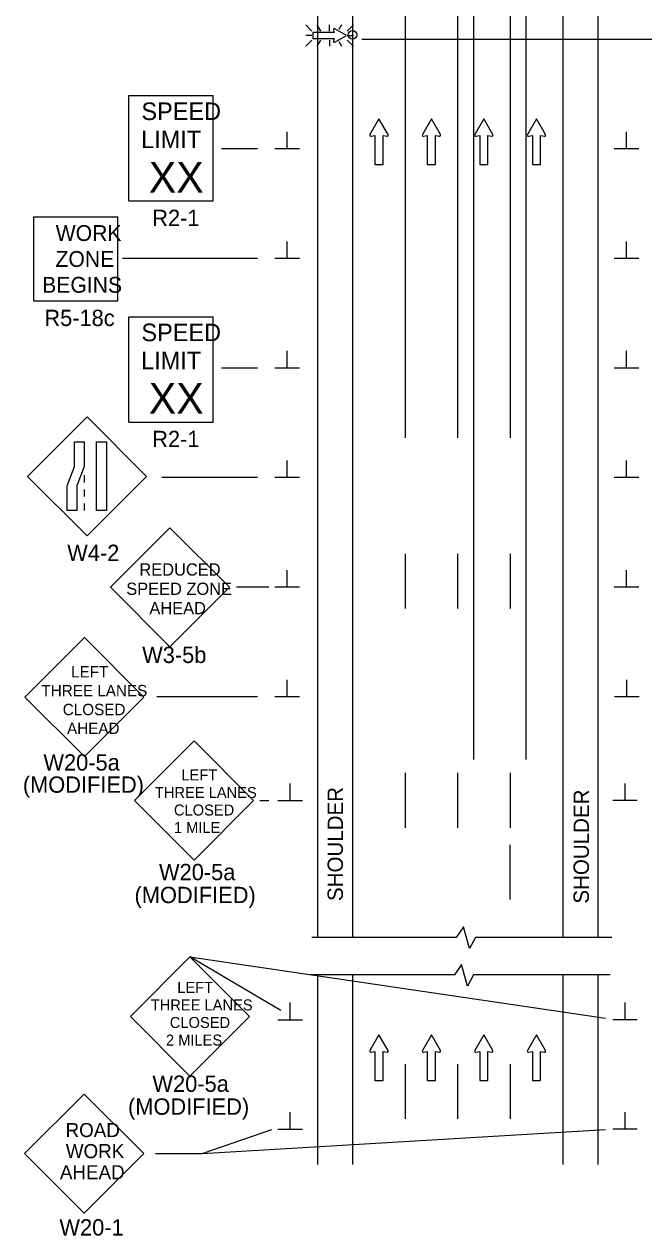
# Model space of a CAD drawing. Extents: x 16725 to 18479, y 5932 to 7023.
# Drawn here: x 16725 to 17008, y 5959 to 6512 of the extents above; entities that cross this region are included whole.
import ezdxf

# ---------------------------------------------------------------- set-up
doc = ezdxf.new("R2010")
doc.units = 0
for name, color, linetype in [('ALI_LEGAL_EX', 7, 'Continuous'), ('MT_SCRATCH_LEVEL_E', 7, 'Continuous'), ('PAVT_EDGE_EX', 7, 'Continuous'), ('TRAFFIC_SIGNS_PR', 7, 'Continuous'), ('TYPICAL_TEXT_DIMEN_PR', 7, 'Continuous')]:
    doc.layers.add(name, color=color, linetype=linetype)

msp = doc.modelspace()

# ---------------------------------------------------------------- linework, layer by layer
at = {"layer": 'ALI_LEGAL_EX'}
for p, q in [((16898.69, 7022.86), (16898.69, 6323.13)), ((16922.69, 7022.86), (16922.69, 6323.13)), ((16946.69, 7022.86), (16946.69, 6323.13)), ((16929.88, 7005.57), (16929.88, 6176.39)), ((16953.88, 7005.57), (16953.88, 6176.39)), ((16953.88, 7005.57), (16953.88, 6176.39))]:
    msp.add_line(p, q, dxfattribs=at)
for points in [[(16898.69, 6470.26), (16898.69, 6445.26)], [(16922.69, 6470.26), (16922.69, 6445.26)], [(16946.69, 6470.26), (16946.69, 6445.26)], [(16898.69, 6370.26), (16898.69, 6345.26)], [(16922.69, 6370.26), (16922.69, 6345.26)], [(16946.69, 6370.26), (16946.69, 6345.26)], [(16898.69, 6270.26), (16898.69, 6245.26)], [(16922.69, 6270.26), (16922.69, 6245.26)], [(16946.69, 6270.26), (16946.69, 6245.26)], [(16898.69, 6170.26), (16898.69, 6145.26)], [(16922.69, 6170.26), (16922.69, 6145.26)], [(16946.69, 6170.26), (16946.69, 6145.26)], [(16946.69, 6112.44), (16946.69, 6137.44)], [(16898.69, 6037.44), (16898.69, 6012.44)], [(16922.69, 6037.44), (16922.69, 6012.44)], [(16946.69, 6037.44), (16946.69, 6012.44)]]:
    msp.add_lwpolyline(points, dxfattribs=at)
at = {"layer": 'MT_SCRATCH_LEVEL_E'}
for p, q in [((16886.79, 6468.72), (16882.68, 6461.48)), ((16890.94, 6461.48), (16886.79, 6468.72)), ((16910.69, 6468.72), (16906.58, 6461.48)), ((16914.84, 6461.48), (16910.69, 6468.72)), ((16934.6, 6468.72), (16930.49, 6461.48)), ((16938.74, 6461.48), (16934.6, 6468.72)), ((16958.65, 6468.72), (16954.54, 6461.48)), ((16962.8, 6461.48), (16958.65, 6468.72)), ((16883.16, 6460.79), (16884.94, 6461.11)), ((16884.94, 6461.11), (16884.94, 6447.85)), ((16888.68, 6447.85), (16888.68, 6461.11)), ((16888.68, 6461.11), (16890.46, 6460.79)), ((16907.06, 6460.79), (16908.84, 6461.11)), ((16908.84, 6461.11), (16908.84, 6447.85)), ((16912.58, 6447.85), (16912.58, 6461.11)), ((16912.58, 6461.11), (16914.36, 6460.79)), ((16930.97, 6460.79), (16932.74, 6461.11)), ((16932.74, 6461.11), (16932.74, 6447.85)), ((16936.49, 6447.85), (16936.49, 6461.11)), ((16936.49, 6461.11), (16938.26, 6460.79)), ((16955.02, 6460.79), (16956.8, 6461.11)), ((16956.8, 6461.11), (16956.8, 6447.85)), ((16960.54, 6447.85), (16960.54, 6461.11)), ((16960.54, 6461.11), (16962.32, 6460.79)), ((16884.94, 6447.85), (16888.68, 6447.85)), ((16908.84, 6447.85), (16912.58, 6447.85)), ((16932.74, 6447.85), (16936.49, 6447.85)), ((16956.8, 6447.85), (16960.54, 6447.85)), ((16886.79, 6050.8), (16882.68, 6043.56)), ((16890.94, 6043.56), (16886.79, 6050.8)), ((16910.69, 6050.8), (16906.58, 6043.56)), ((16914.84, 6043.56), (16910.69, 6050.8)), ((16934.6, 6050.8), (16930.49, 6043.56)), ((16938.74, 6043.56), (16934.6, 6050.8)), ((16958.65, 6050.8), (16954.54, 6043.56)), ((16962.8, 6043.56), (16958.65, 6050.8)), ((16883.16, 6042.87), (16884.94, 6043.19)), ((16884.94, 6043.19), (16884.94, 6029.93)), ((16888.68, 6029.93), (16888.68, 6043.19)), ((16888.68, 6043.19), (16890.46, 6042.87)), ((16907.06, 6042.87), (16908.84, 6043.19)), ((16908.84, 6043.19), (16908.84, 6029.93)), ((16912.58, 6029.93), (16912.58, 6043.19)), ((16912.58, 6043.19), (16914.36, 6042.87)), ((16930.97, 6042.87), (16932.74, 6043.19)), ((16932.74, 6043.19), (16932.74, 6029.93)), ((16936.49, 6029.93), (16936.49, 6043.19)), ((16936.49, 6043.19), (16938.26, 6042.87)), ((16955.02, 6042.87), (16956.8, 6043.19)), ((16956.8, 6043.19), (16956.8, 6029.93)), ((16960.54, 6029.93), (16960.54, 6043.19)), ((16960.54, 6043.19), (16962.32, 6042.87)), ((16884.94, 6029.93), (16888.68, 6029.93)), ((16908.84, 6029.93), (16912.58, 6029.93)), ((16932.74, 6029.93), (16936.49, 6029.93)), ((16956.8, 6029.93), (16960.54, 6029.93))]:
    msp.add_line(p, q, dxfattribs=at)
for centre, start, end in [((16883.09, 6461.25), 150.4248, 279.9638), ((16890.53, 6461.25), 260.0362, 29.7731), ((16906.99, 6461.25), 150.4248, 279.9638), ((16914.43, 6461.25), 260.0362, 29.7731), ((16930.89, 6461.25), 150.4248, 279.9638), ((16938.33, 6461.25), 260.0362, 29.7731), ((16954.95, 6461.25), 150.4248, 279.9638), ((16962.39, 6461.25), 260.0362, 29.7731), ((16883.09, 6043.33), 150.4248, 279.9638), ((16890.53, 6043.33), 260.0362, 29.7731), ((16906.99, 6043.33), 150.4248, 279.9638), ((16914.43, 6043.33), 260.0362, 29.7731), ((16930.89, 6043.33), 150.4248, 279.9638), ((16938.33, 6043.33), 260.0362, 29.7731), ((16954.95, 6043.33), 150.4248, 279.9638), ((16962.39, 6043.33), 260.0362, 29.7731)]:
    msp.add_arc(centre, 0.463, start, end, dxfattribs=at)
at = {"layer": 'PAVT_EDGE_EX'}
for p, q in [((16858.69, 6927.61), (16858.69, 6189.52)), ((16874.69, 6927.61), (16874.69, 6189.52)), ((16970.69, 6927.61), (16970.69, 6189.52)), ((16986.69, 6927.61), (16986.69, 6189.52)), ((16858.69, 6189.52), (16858.69, 6095.26)), ((16874.69, 6189.52), (16874.69, 6095.26)), ((16970.69, 6189.52), (16970.69, 6095.25)), ((16986.69, 6189.52), (16986.69, 6095.25)), ((16858.69, 6078.1), (16858.69, 5991.64)), ((16874.69, 6078.1), (16874.69, 5991.64)), ((16970.69, 6078.11), (16970.69, 5991.64)), ((16986.69, 6078.11), (16986.69, 5991.64))]:
    msp.add_line(p, q, dxfattribs=at)
at = {"layer": 'TRAFFIC_SIGNS_PR'}
for p, q in [((16856.17, 6508.7), (16853.35, 6511.52)), ((16858.47, 6511.52), (16860.1, 6508.7)), ((16864.26, 6508.7), (16864.26, 6511.52)), ((16869.73, 6511.52), (16868.52, 6509.43)), ((16875.16, 6511.52), (16872.34, 6508.7)), ((16856.17, 6506.67), (16853.35, 6506.67)), ((16872.34, 6506.67), (16875.16, 6506.67)), ((16856.17, 6504.64), (16853.35, 6501.81)), ((16860.12, 6504.64), (16858.49, 6501.82)), ((16864.26, 6504.64), (16864.26, 6501.82)), ((16868.44, 6504), (16869.7, 6501.82)), ((16875.16, 6501.82), (16872.34, 6504.64)), ((16772.61, 6479.27), (16811.05, 6479.27)), ((16772.61, 6431.21), (16772.61, 6479.27)), ((16811.05, 6431.21), (16811.05, 6479.27)), ((16772.61, 6431.21), (16811.05, 6431.21)), ((16729.26, 6385.58), (16729.26, 6423.98)), ((16729.26, 6423.98), (16767.66, 6423.98)), ((16767.66, 6385.58), (16767.66, 6423.98)), ((16729.26, 6385.58), (16767.66, 6385.58)), ((16772.61, 6378.4), (16811.06, 6378.4)), ((16772.61, 6330.34), (16772.61, 6378.4)), ((16811.06, 6330.34), (16811.06, 6378.4)), ((16753.55, 6332.69), (16726.39, 6305.54)), ((16780.7, 6305.54), (16753.55, 6332.69)), ((16772.61, 6330.34), (16811.06, 6330.34)), ((16726.39, 6305.54), (16753.55, 6278.39)), ((16752.3, 6306.03), (16752.3, 6302.83)), ((16753.55, 6278.39), (16780.7, 6305.54)), ((16752.3, 6299.63), (16752.3, 6296.43)), ((16752.3, 6293.23), (16752.3, 6290.03)), ((16791.39, 6282.1), (16764.24, 6254.95)), ((16818.55, 6254.95), (16791.39, 6282.1)), ((16764.24, 6254.95), (16791.39, 6227.8)), ((16791.39, 6227.8), (16818.55, 6254.95)), ((16752.34, 6232.01), (16725.19, 6204.86)), ((16779.5, 6204.86), (16752.34, 6232.01)), ((16725.19, 6204.86), (16752.34, 6177.7)), ((16752.34, 6177.7), (16779.5, 6204.86)), ((16802.37, 6184.87), (16775.19, 6157.68)), ((16829.56, 6157.68), (16802.37, 6184.87)), ((16775.19, 6157.68), (16802.37, 6130.5)), ((16802.37, 6130.5), (16829.56, 6157.68)), ((16800.49, 6086.29), (16773.31, 6059.11)), ((16827.68, 6059.11), (16800.49, 6086.29)), ((16773.31, 6059.11), (16800.49, 6031.92)), ((16800.49, 6031.92), (16827.68, 6059.11)), ((16752.23, 6023.74), (16725.04, 5996.56)), ((16779.42, 5996.56), (16752.23, 6023.74)), ((16725.04, 5996.56), (16752.23, 5969.37)), ((16752.23, 5969.37), (16779.42, 5996.56))]:
    msp.add_line(p, q, dxfattribs=at)
for points in [[(16866.08, 6509.35), (16866.31, 6508.05), (16856.59, 6508.05), (16856.59, 6505.31), (16866.31, 6505.31), (16866.08, 6504.01)], [(16866.58, 6503.65), (16871.89, 6506.67), (16866.58, 6509.71)]]:
    msp.add_lwpolyline(points, dxfattribs=at)
for points in [[(16752.3, 6321.28), (16752.3, 6310.1), (16748.95, 6301.21), (16748.95, 6290.03), (16744.46, 6290.03), (16744.46, 6301.21), (16747.8, 6310.1), (16747.8, 6321.28)], [(16762.43, 6321.28), (16762.43, 6290.03), (16757.94, 6290.03), (16757.94, 6321.28)]]:
    msp.add_lwpolyline(points, close=True, dxfattribs=at)
msp.add_circle((16874.7, 6507.03), 2, dxfattribs=at)
for centre, start, end in [((16866.42, 6509.41), 61.4833, 189.9593), ((16866.42, 6503.95), 170.7308, 298.8916)]:
    msp.add_arc(centre, 0.341, start, end, dxfattribs=at)
at = {"layer": 'TYPICAL_TEXT_DIMEN_PR'}
for p, q in [((16878.96, 6504.98), (17062.74, 6504.98)), ((16907.09, 6504.98), (17061.13, 6504.98)), ((16844.81, 6454.98), (16844.81, 6462.77)), ((16999.82, 6454.98), (16999.82, 6462.77)), ((16831.38, 6454.98), (16814.89, 6454.98)), ((16850.44, 6454.98), (16839.19, 6454.98)), ((17005.44, 6454.98), (16994.19, 6454.98)), ((16844.81, 6404.98), (16844.81, 6412.77)), ((16999.82, 6404.98), (16999.82, 6412.77)), ((16831.38, 6404.98), (16769.78, 6404.98)), ((16850.44, 6404.98), (16839.19, 6404.98)), ((17005.44, 6404.98), (16994.19, 6404.98)), ((16844.81, 6354.98), (16844.81, 6362.77)), ((16999.82, 6354.98), (16999.82, 6362.77)), ((16831.38, 6354.98), (16814.89, 6354.98)), ((16850.44, 6354.98), (16839.19, 6354.98)), ((17005.44, 6354.98), (16994.19, 6354.98)), ((16844.81, 6304.98), (16844.81, 6312.77)), ((16999.82, 6304.98), (16999.82, 6312.77)), ((16831.38, 6304.98), (16787.72, 6304.98)), ((16850.44, 6304.98), (16839.19, 6304.98)), ((17005.44, 6304.98), (16994.19, 6304.98)), ((16844.81, 6254.98), (16844.81, 6262.77)), ((16999.82, 6254.98), (16999.82, 6262.77)), ((16836.48, 6254.98), (16821.8, 6254.98)), ((16850.44, 6254.98), (16839.19, 6254.98)), ((17005.44, 6254.98), (16994.19, 6254.98)), ((16844.95, 6204.98), (16844.95, 6212.77)), ((16999.96, 6204.98), (16999.96, 6212.77)), ((16831.38, 6204.98), (16785.46, 6204.98)), ((16850.57, 6204.98), (16839.32, 6204.98)), ((17005.58, 6204.98), (16994.33, 6204.98)), ((16846.32, 6157.67), (16846.32, 6165.46)), ((16999.07, 6157.67), (16999.07, 6165.46)), ((16836.48, 6157.57), (16832.38, 6157.57)), ((16840.69, 6157.67), (16851.94, 6157.67)), ((17004.69, 6157.67), (16993.44, 6157.67)), ((16925.31, 6100.03), (16922.05, 6095.23)), ((16928.05, 6090.1), (16925.31, 6100.03)), ((16922.05, 6095.23), (16856.11, 6095.23)), ((16930.79, 6095.23), (16928.05, 6090.1)), ((16993.12, 6095.23), (16930.79, 6095.23)), ((16841.93, 6061.85), (16800.49, 6086.29)), ((16800.49, 6086.29), (16990.17, 6058.35)), ((16924.51, 6082.9), (16921.25, 6078.1)), ((16927.25, 6072.96), (16924.51, 6082.9)), ((16921.25, 6078.1), (16855.31, 6078.1)), ((16929.99, 6078.1), (16927.25, 6072.96)), ((16992.32, 6078.1), (16929.99, 6078.1)), ((16846.32, 6057.67), (16846.32, 6065.46)), ((16999.07, 6057.67), (16999.07, 6065.46)), ((16840.69, 6057.67), (16851.94, 6057.67)), ((17004.69, 6057.67), (16993.44, 6057.67)), ((16846.32, 6007.67), (16846.32, 6015.46)), ((16999.07, 6007.67), (16999.07, 6015.46)), ((16806.09, 5996.56), (16837.85, 6007.58)), ((16806.09, 5996.56), (16990.17, 6007.58)), ((16840.69, 6007.67), (16851.94, 6007.67)), ((17004.69, 6007.67), (16993.44, 6007.67)), ((16784.83, 5996.56), (16806.09, 5996.56))]:
    msp.add_line(p, q, dxfattribs=at)

# ---------------------------------------------------------------- texts
at = {"layer": 'TRAFFIC_SIGNS_PR'}
for s, height, p in [('SPEED', 8.01, (16778.38, 6468.12)), ('LIMIT', 8.01, (16778.22, 6455.31)), ('XX', 14.048, (16781.73, 6434.98)), ('R2-1', 7.449, (16783.3, 6419.76)), ('WORK', 7.217, (16739.26, 6412.95)), ('ZONE', 7.217, (16739.15, 6401.14)), ('BEGINS', 7.217, (16733.07, 6389.33)), ('R5-18c', 7.44, (16734.08, 6374.14)), ('SPEED', 8.01, (16778.38, 6367.24)), ('LIMIT', 8.01, (16778.22, 6354.43)), ('XX', 14.048, (16781.73, 6334.1)), ('R2-1', 7.449, (16783.3, 6318.88)), ('W4-2', 7.44, (16744.5, 6266.95)), ('REDUCED', 5.6, (16777.45, 6260.26)), ('SPEED ZONE', 5.6, (16771.44, 6251.46)), ('AHEAD', 5.6, (16782, 6242.66)), ('W3-5b', 7.44, (16778.71, 6220.39)), ('LEFT', 5.2, (16746.29, 6213.79)), ('THREE LANES', 5.2, (16732.74, 6205.19)), ('CLOSED', 5.2, (16742.47, 6196.59)), ('AHEAD', 5.2, (16744.41, 6187.99)), ('W20-5a', 7.44, (16733.65, 6171.32)), ('(MODIFIED)', 7.44, (16724.26, 6161.21)), ('LEFT', 5.006, (16796.62, 6166.84)), ('THREE LANES', 5.0062, (16784.5, 6158.83)), ('CLOSED', 5.006, (16793.2, 6150.82)), ('1 MILE', 5.006, (16793.19, 6142.82)), ('W20-5a', 7.449, (16786.38, 6121.3)), ('(MODIFIED)', 7.449, (16775.22, 6110.85)), ('LEFT', 5.006, (16794.74, 6069.91)), ('THREE LANES', 5.0062, (16782.62, 6061.9)), ('CLOSED', 5.006, (16791.32, 6053.89)), ('2 MILES', 5.006, (16789.56, 6045.88)), ('W20-5a', 7.449, (16783.4, 6024.75)), ('(MODIFIED)', 7.449, (16772.24, 6014.3)), ('ROAD', 6.408, (16743.76, 6004.1)), ('WORK', 6.408, (16743.87, 5994.49)), ('AHEAD', 6.408, (16741.18, 5984.88)), ('W20-1', 7.449, (16740.95, 5959.19))]:
    msp.add_text(s, height=height, dxfattribs=at).set_placement(p)
at = {"layer": 'TYPICAL_TEXT_DIMEN_PR'}
for p in [(16870.32, 6111.81), (16982.59, 6110.64)]:
    msp.add_text('SHOULDER', height=7, rotation=90, dxfattribs=at).set_placement(p)

doc.saveas('drawing.dxf')
